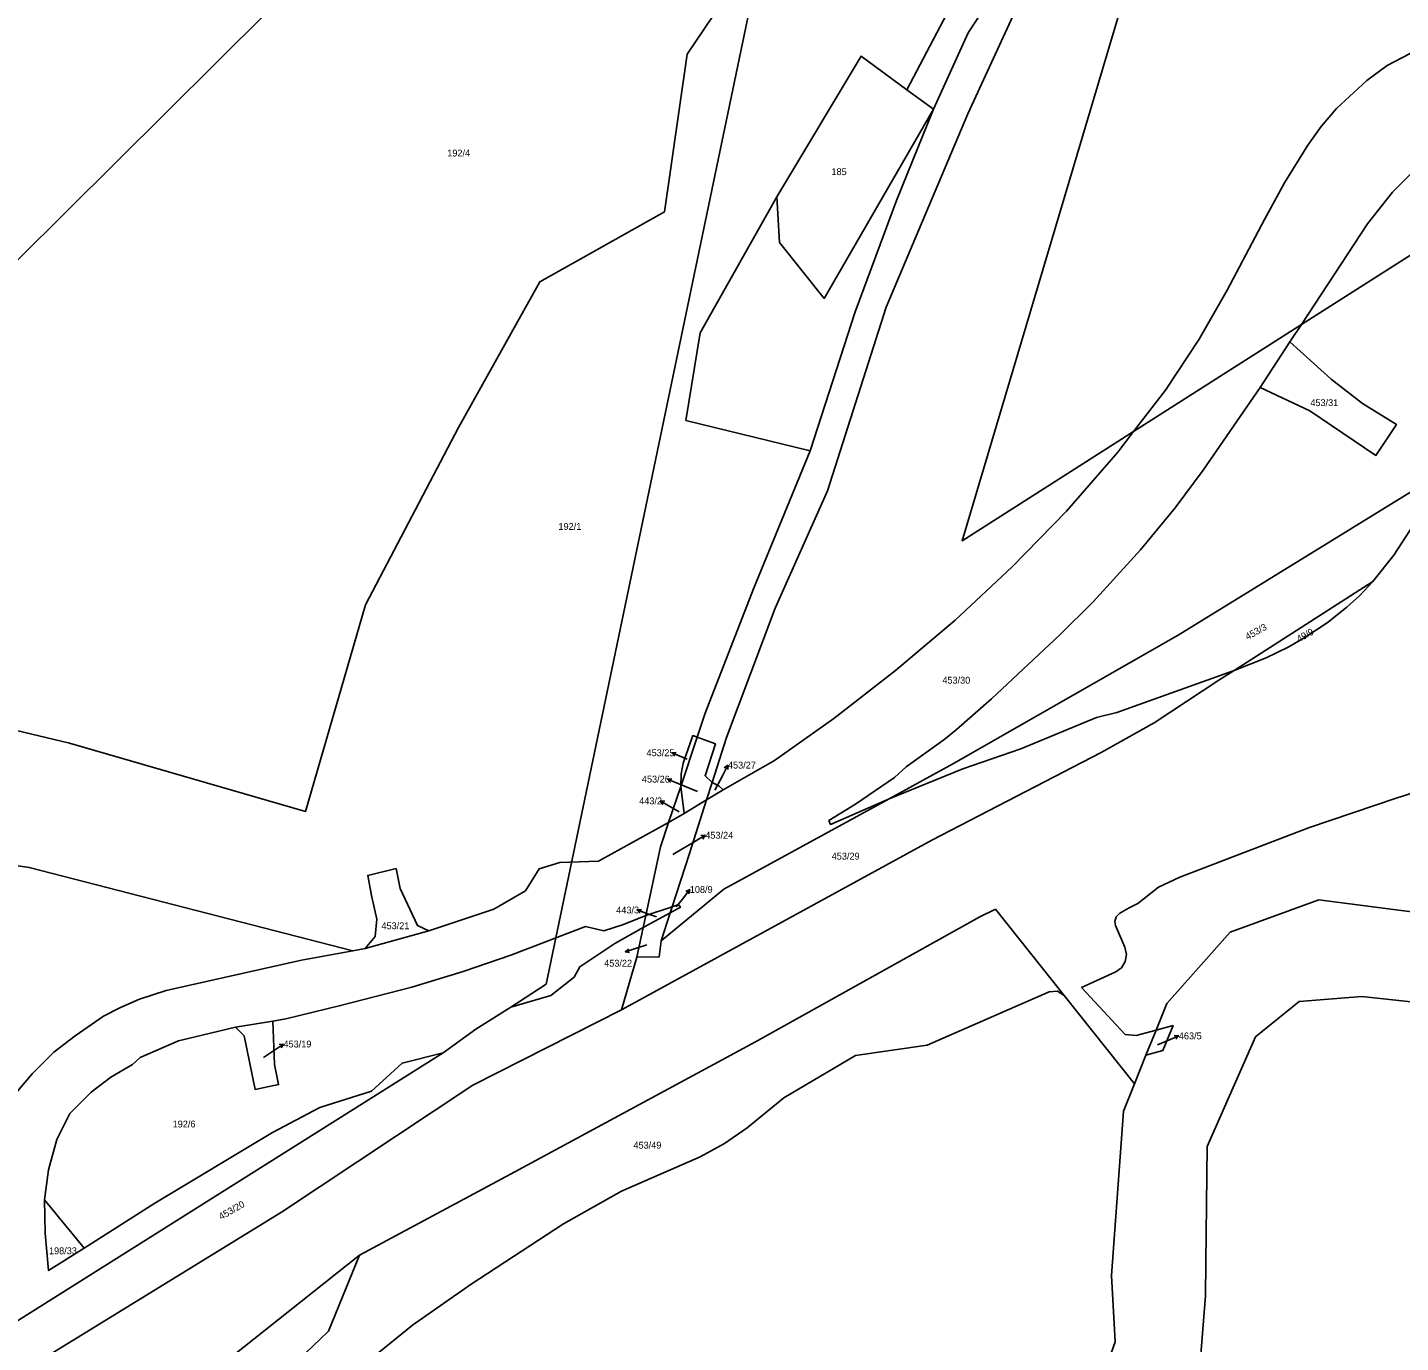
# Model space of a CAD drawing. Extents: x -882150 to -879379, y -1022570 to -1019819.
# Drawn here: x -880457.2 to -880115.3, y -1021005.3 to -1020677.8 of the extents above; entities that cross this region are included whole.
import ezdxf

# ---------------------------------------------------------------- set-up
doc = ezdxf.new("R2010")
doc.units = 0
for name, color, linetype in [('Hranice parcel', 7, 'Continuous'), ('Parcelní čísla', 7, 'Continuous'), ('Pop  PČ popisy', 7, 'Continuous'), ('Vnitřní kresba', 7, 'Continuous')]:
    doc.layers.add(name, color=color, linetype=linetype)

msp = doc.modelspace()

# ---------------------------------------------------------------- linework, layer by layer
at = {"layer": 'Hranice parcel'}
for p, q in [((-880238.27, -1020693.28), (-880231.63, -1020698.12)), ((-880181.75, -1020778.37), (-880139.93, -1020751.73)), ((-880139.93, -1020751.73), (-880142.83, -1020756.07)), ((-880142.83, -1020756.07), (-880150.22, -1020767.47)), ((-880122.17, -1020815.79), (-880156.76, -1020837.93)), ((-880294.53, -1020866.79), (-880290.44, -1020854.54)), ((-880294.53, -1020866.79), (-880297.54, -1020875.81)), ((-880293.68, -1020873.57), (-880294.53, -1020866.79)), ((-880288.1, -1020870.15), (-880286.7, -1020865.81)), ((-880288.1, -1020870.15), (-880283.97, -1020867.62)), ((-880293.68, -1020873.57), (-880288.1, -1020870.15)), ((-880297.54, -1020875.81), (-880293.68, -1020873.57)), ((-880303.88, -1020901.94), (-880297.16, -1020898.25)), ((-880303.88, -1020901.94), (-880303.23, -1020898.93)), ((-880296.68, -1020896.77), (-880303.23, -1020898.93)), ((-880299.42, -1020905.23), (-880297.16, -1020898.25)), ((-880296.68, -1020896.77), (-880297.16, -1020898.25)), ((-880216.12, -1020897.39), (-880199.05, -1020918.85)), ((-880373.11, -1020907.18), (-880357.27, -1020902.75)), ((-880305.47, -1020909.34), (-880303.88, -1020901.94)), ((-880376.21, -1020907.74), (-880373.11, -1020907.18)), ((-880309.24, -1020922.47), (-880305.47, -1020909.34)), ((-880181.53, -1020940.86), (-880199.05, -1020918.85)), ((-880140.53, -1020920.39), (-880124.94, -1020919.09)), ((-880396.06, -1020925.22), (-880405.41, -1020926.73)), ((-880176.17, -1020927.49), (-880178.69, -1020933.76)), ((-880181.53, -1020940.86), (-880178.69, -1020933.76)), ((-880452.92, -1020969.75), (-880443.03, -1020981.82)), ((-880163.83, -1020993.67), (-880163.75, -1020985.47))]:
    msp.add_line(p, q, dxfattribs=at)
for points in [[(-880181.75, -1020778.37), (-880224.49, -1020805.59), (-880179.88, -1020655.79), (-880135.29, -1020506), (-880090.68, -1020356.2)], [(-880169.37, -1020529.41), (-880177.43, -1020555.79), (-880182.92, -1020584.5), (-880189.9, -1020614), (-880200.18, -1020646.83), (-880206.84, -1020664.08), (-880223.08, -1020699.25), (-880243.38, -1020747.4), (-880257.98, -1020793.2), (-880271.05, -1020822.37), (-880283.1, -1020854.61), (-880286.7, -1020865.81)], [(-880360.27, -1020636.82), (-880354.1, -1020637.87), (-880321.84, -1020610.85), (-880294.54, -1020587.99), (-880281.75, -1020603.26), (-880254.56, -1020635.3), (-880265.26, -1020654.96), (-880284.47, -1020671.92), (-880292.9, -1020684.4), (-880298.58, -1020723.73), (-880329.61, -1020741.11), (-880349.9, -1020777.37), (-880372.99, -1020821.6), (-880387.98, -1020873.06), (-880446.75, -1020856.01), (-880505.51, -1020841.96)], [(-880360.27, -1020636.82), (-880459.8, -1020735.88), (-880505.51, -1020841.96)], [(-880210.36, -1020645.27), (-880221.64, -1020661.69), (-880238.27, -1020693.28)], [(-880231.63, -1020698.12), (-880222.93, -1020679.1), (-880211.66, -1020661.81), (-880205.85, -1020646.77)], [(-880111.13, -1020683.34), (-880118.61, -1020687.27), (-880123.66, -1020691.01), (-880131.25, -1020697.94), (-880135.05, -1020702.48), (-880138.42, -1020707.13), (-880144.23, -1020716.46), (-880149.21, -1020725.58), (-880158.47, -1020743.21), (-880165.4, -1020755.39), (-880173.83, -1020768.13), (-880181.75, -1020778.37)], [(-880238.27, -1020693.28), (-880249.64, -1020684.93), (-880270.59, -1020719.96)], [(-880290.44, -1020854.54), (-880288.44, -1020848.53), (-880276.39, -1020817.55), (-880262.3, -1020783.21), (-880251.07, -1020748.62), (-880240.78, -1020720.89), (-880231.63, -1020698.12)], [(-880270.59, -1020719.96), (-880269.91, -1020731.31), (-880258.78, -1020745.24), (-880231.63, -1020698.12)], [(-880070.77, -1020713.27), (-880069.41, -1020711.42), (-880069.23, -1020708.91), (-880070.33, -1020706.52), (-880072.26, -1020705.33), (-880078.68, -1020703.61), (-880086.33, -1020703.09), (-880092.94, -1020703.88), (-880100.29, -1020706.14), (-880106.13, -1020709.1), (-880111.46, -1020713.02), (-880117.31, -1020718.77), (-880123.56, -1020726.71), (-880139.93, -1020751.73)], [(-880139.93, -1020751.73), (-880094.28, -1020722.66), (-880085.25, -1020734.33)], [(-880150.22, -1020767.47), (-880137.88, -1020773.22), (-880121.41, -1020784.35), (-880116.31, -1020776.65), (-880124.8, -1020771.46), (-880132.61, -1020765.33), (-880142.83, -1020756.07)], [(-880150.22, -1020767.47), (-880164.46, -1020787.99), (-880171.43, -1020797.37), (-880180.08, -1020807.88), (-880191.83, -1020820.82), (-880200.11, -1020829.08), (-880217.14, -1020844.96), (-880225.91, -1020852.71), (-880229.02, -1020855.16), (-880238.4, -1020861.93), (-880241.26, -1020864.61), (-880251, -1020871.19), (-880257.64, -1020875.29), (-880257.26, -1020876.25), (-880242.62, -1020869.86)], [(-880283.97, -1020867.62), (-880271.21, -1020860.33), (-880256.37, -1020849.85), (-880241.06, -1020837.88), (-880226.22, -1020825.37), (-880212.01, -1020812.14), (-880198.47, -1020798.2), (-880185.73, -1020783.52), (-880181.75, -1020778.37)], [(-880242.62, -1020869.86), (-880226.61, -1020861.09), (-880170.66, -1020829.12), (-880104.98, -1020788.72)], [(-880104.98, -1020788.72), (-880110.84, -1020799.71), (-880116.96, -1020809.22), (-880122.17, -1020815.79)], [(-879855.67, -1020806.93), (-879897.91, -1020816.71), (-879991.04, -1020835.27), (-880061.88, -1020853.33), (-880091.47, -1020861.88), (-880116.15, -1020869.62), (-880138.18, -1020877.13), (-880170.25, -1020889.4), (-880175.6, -1020891.87), (-880180.75, -1020895.93), (-880182.85, -1020897), (-880185.19, -1020898.34), (-880186.1, -1020899.24), (-880186.44, -1020900.39), (-880186.27, -1020901.44), (-880183.95, -1020906.85), (-880183.54, -1020908.65), (-880183.84, -1020910.43), (-880184.81, -1020911.94), (-880186.2, -1020912.94), (-880194.71, -1020916.87), (-880183.87, -1020928.56), (-880181.15, -1020928.81), (-880176.17, -1020927.49)], [(-880176.17, -1020927.49), (-880173.52, -1020920.87), (-880157.73, -1020903.11), (-880135.62, -1020895), (-880066.31, -1020904.04), (-880020.56, -1020909.99), (-879978.51, -1020931.21), (-879954.91, -1020940.95), (-879934.91, -1020941.76), (-879915.17, -1020933.91), (-879891.35, -1020908.94), (-879871.04, -1020869.47), (-879858.22, -1020838.74), (-879867.14, -1020822.1), (-879855.67, -1020806.93)], [(-880156.76, -1020837.93), (-880148.73, -1020834.8), (-880143.26, -1020832.13), (-880139.12, -1020829.73), (-880133.59, -1020826.04), (-880128.64, -1020822.14), (-880125.43, -1020819.23), (-880122.17, -1020815.79)], [(-880156.76, -1020837.93), (-880160.51, -1020840.33), (-880176.62, -1020850.96), (-880189.88, -1020858.38), (-880232.02, -1020880.14), (-880309.24, -1020922.47)], [(-880242.62, -1020869.86), (-880224.31, -1020862.41), (-880209.84, -1020857.43), (-880190.99, -1020849.61), (-880185.98, -1020848.36), (-880156.76, -1020837.93)], [(-880290.44, -1020854.54), (-880291.53, -1020854.15), (-880293.93, -1020861.01), (-880294.41, -1020863.62), (-880294.53, -1020866.79)], [(-880286.7, -1020865.81), (-880288.47, -1020864.12), (-880285.87, -1020856.15), (-880290.44, -1020854.54)], [(-880283.97, -1020867.62), (-880285, -1020866.63), (-880286.7, -1020865.81)], [(-880517.75, -1020870.05), (-880517.49, -1020870.11), (-880505.07, -1020880.11), (-880491.9, -1020885.09), (-880485.69, -1020882.64), (-880456.73, -1020886.98), (-880376.21, -1020907.74)], [(-880242.62, -1020869.86), (-880283.79, -1020892.4), (-880299.42, -1020905.23)], [(-880296.68, -1020896.77), (-880292.38, -1020883.47), (-880288.1, -1020870.15)], [(-880357.27, -1020902.75), (-880341.1, -1020897.36), (-880333.18, -1020892.77), (-880329.77, -1020887.29), (-880324.59, -1020885.71), (-880314.97, -1020885.37), (-880297.54, -1020875.81)], [(-880303.23, -1020898.93), (-880299.56, -1020881.85), (-880297.54, -1020875.81)], [(-880357.27, -1020902.75), (-880360.03, -1020901.45), (-880364.41, -1020892.19), (-880365.39, -1020887.26), (-880372.44, -1020888.94), (-880371.54, -1020893.97), (-880370.18, -1020899.85), (-880370.57, -1020904.19), (-880373.11, -1020907.18)], [(-880303.23, -1020898.93), (-880308.74, -1020901.14), (-880313.66, -1020902.75), (-880318.22, -1020901.68), (-880336.8, -1020908.79), (-880348.72, -1020912.89), (-880361.47, -1020916.77), (-880379.22, -1020921.37), (-880392.88, -1020924.69), (-880396.06, -1020925.22)], [(-880374.5, -1020983.56), (-880336.91, -1020963.36), (-880275.89, -1020930.37), (-880220.08, -1020899.26), (-880216.12, -1020897.39)], [(-880297.16, -1020898.25), (-880294.62, -1020896.87), (-880295.09, -1020896.22), (-880296.68, -1020896.77)], [(-880443.03, -1020981.82), (-880425.47, -1020970.54), (-880396.18, -1020953.01), (-880384.39, -1020946.77), (-880371.56, -1020942.65), (-880363.91, -1020935.7), (-880353.65, -1020933.14), (-880345.53, -1020927.28), (-880336.82, -1020921.74), (-880326.9, -1020918.86), (-880321.06, -1020914.29), (-880319.61, -1020911.72), (-880310.91, -1020905.88), (-880303.88, -1020901.94)], [(-880305.47, -1020909.34), (-880299.93, -1020909.24), (-880299.42, -1020905.23)], [(-880461.45, -1020945.38), (-880459.21, -1020942.16), (-880455.97, -1020938.25), (-880450.62, -1020932.96), (-880445.34, -1020928.88), (-880438.23, -1020924.03), (-880433.98, -1020921.88), (-880429.27, -1020919.8), (-880422.63, -1020917.62), (-880388.94, -1020910.08), (-880376.21, -1020907.74)], [(-880199.05, -1020918.85), (-880200.75, -1020917.75), (-880202.77, -1020917.97), (-880233.19, -1020931.27), (-880251.05, -1020933.81), (-880268.87, -1020944.34), (-880277.99, -1020951.78), (-880283.59, -1020955.76), (-880289.65, -1020959.07), (-880309.25, -1020967.57), (-880323.7, -1020975.72), (-880346.68, -1020990.73), (-880361.3, -1021000.94), (-880371.02, -1021008.81), (-880386.57, -1021024.64)], [(-880124.94, -1020919.09), (-880036, -1020928.73), (-880013.41, -1020937.59)], [(-880309.24, -1020922.47), (-880346.3, -1020941.23), (-880393.91, -1020972.78), (-880481.22, -1021026.44)], [(-880163.75, -1020985.47), (-880163.48, -1020956.44), (-880151.41, -1020929.13), (-880140.53, -1020920.39)], [(-880405.41, -1020926.73), (-880419.61, -1020930.15), (-880429.15, -1020934.34), (-880431.01, -1020936.05), (-880436.4, -1020939.22), (-880441.32, -1020942.92), (-880446.63, -1020948.21), (-880449.85, -1020954.72), (-880451.96, -1020962.25), (-880452.92, -1020969.75)], [(-880396.06, -1020925.22), (-880395.65, -1020936.08), (-880394.64, -1020941.05), (-880400.52, -1020942.24), (-880403.23, -1020928.94), (-880405.41, -1020926.73)], [(-880178.69, -1020933.76), (-880174.48, -1020932.59), (-880171.94, -1020926.36), (-880176.17, -1020927.49)], [(-880352.16, -1021204.62), (-880345.13, -1021178.51), (-880333.62, -1021140.15), (-880320.84, -1021109.45), (-880307.78, -1021088.71), (-880291.73, -1021075.46), (-880275.49, -1021067.81), (-880232.91, -1021051.56), (-880209.2, -1021040.29), (-880193.39, -1021025.06), (-880186.35, -1021005.08), (-880187.25, -1020988.59), (-880184.26, -1020947.68), (-880181.53, -1020940.86)], [(-880452.92, -1020969.75), (-880452.8, -1020978.03), (-880451.91, -1020987.37), (-880443.03, -1020981.82)], [(-880574.71, -1021116.82), (-880511.95, -1021078.31), (-880468.39, -1021050.82), (-880418.11, -1021018.15), (-880374.5, -1020983.56)], [(-880374.5, -1020983.56), (-880382.21, -1021002.48), (-880395.74, -1021015.43), (-880410.24, -1021024.49)], [(-880383.32, -1021590.53), (-880388.97, -1021562.43), (-880390.19, -1021534.27), (-880387.73, -1021505.59), (-880379.83, -1021478.12), (-880354.56, -1021409.73), (-880325.92, -1021331.12), (-880321.65, -1021310.18), (-880321.88, -1021279.76), (-880330.68, -1021225.65), (-880330.04, -1021210.18), (-880313.87, -1021148.79), (-880301.09, -1021117.72), (-880281.33, -1021095.35), (-880255.32, -1021084.31), (-880230.68, -1021082.99), (-880217.42, -1021078.67), (-880186.94, -1021050.63), (-880171.67, -1021029), (-880165.07, -1021009.24), (-880163.83, -1020993.67)]]:
    msp.add_lwpolyline(points, dxfattribs=at)
at = {"layer": 'Pop  PČ popisy'}
for p, q in [((-880296.742, -1020858.436), (-880295.626, -1020858.347)), ((-880293.96, -1020859.56), (-880296.742, -1020858.436)), ((-880296.742, -1020858.436), (-880296.002, -1020859.275)), ((-880292.91, -1020859.99), (-880293.96, -1020859.56)), ((-880284.15, -1020864.15), (-880282.788, -1020861.476)), ((-880282.788, -1020861.476), (-880283.688, -1020862.141)), ((-880282.788, -1020861.476), (-880282.796, -1020862.596)), ((-880297.822, -1020864.996), (-880296.706, -1020864.907)), ((-880295.04, -1020866.12), (-880297.822, -1020864.996)), ((-880297.822, -1020864.996), (-880297.082, -1020865.835)), ((-880286.01, -1020867.73), (-880284.15, -1020864.15)), ((-880290.33, -1020868.06), (-880295.04, -1020866.12)), ((-880297.04, -1020871.89), (-880299.639, -1020870.39)), ((-880299.639, -1020870.39), (-880298.521, -1020870.457)), ((-880299.639, -1020870.39), (-880299.022, -1020871.324)), ((-880294.9, -1020873.13), (-880297.04, -1020871.89)), ((-880296.48, -1020883.77), (-880291, -1020880.49)), ((-880291, -1020880.49), (-880288.428, -1020878.944)), ((-880288.428, -1020878.944), (-880289.544, -1020879.031)), ((-880288.428, -1020878.944), (-880289.028, -1020879.889)), ((-880294.1, -1020894.83), (-880292.252, -1020892.465)), ((-880292.252, -1020892.465), (-880293.264, -1020892.946)), ((-880292.252, -1020892.465), (-880292.474, -1020893.563)), ((-880295.63, -1020896.82), (-880294.1, -1020894.83)), ((-880305.37, -1020897.564), (-880304.258, -1020897.436)), ((-880302.55, -1020898.59), (-880305.37, -1020897.564)), ((-880305.37, -1020897.564), (-880304.6, -1020898.377)), ((-880300.55, -1020899.31), (-880302.55, -1020898.59)), ((-880305.5, -1020907.06), (-880308.354, -1020907.987)), ((-880308.354, -1020907.987), (-880307.556, -1020907.202)), ((-880308.354, -1020907.987), (-880307.247, -1020908.154)), ((-880303, -1020906.27), (-880305.5, -1020907.06)), ((-880175.82, -1020931.16), (-880173.27, -1020930.08)), ((-880173.27, -1020930.08), (-880170.508, -1020928.907)), ((-880170.508, -1020928.907), (-880171.625, -1020928.838)), ((-880170.508, -1020928.907), (-880171.234, -1020929.76)), ((-880398.38, -1020934.27), (-880395.93, -1020932.62)), ((-880395.93, -1020932.62), (-880393.442, -1020930.942)), ((-880393.442, -1020930.942), (-880394.552, -1020931.087)), ((-880393.442, -1020930.942), (-880393.992, -1020931.917))]:
    msp.add_line(p, q, dxfattribs=at)
at = {"layer": 'Vnitřní kresba'}
for p, q in [((-880328, -1020916), (-880253, -1020556)), ((-880289.67, -1020753.8), (-880270.59, -1020719.96)), ((-880293.24, -1020775.66), (-880289.67, -1020753.8)), ((-880293.24, -1020775.66), (-880262.3, -1020783.21)), ((-880336.82, -1020921.74), (-880328, -1020916)), ((-880345.53, -1020927.28), (-880336.82, -1020921.74)), ((-880353.65, -1020933.14), (-880345.53, -1020927.28)), ((-880497.01, -1021023.34), (-880353.65, -1020933.14))]:
    msp.add_line(p, q, dxfattribs=at)

# ---------------------------------------------------------------- texts
at = {"layer": 'Parcelní čísla'}
for s, p in [('192/4', (-880352.66, -1020709.91)), ('185', (-880257, -1020714.55)), ('453/31', (-880137.76, -1020772.07)), ('192/1', (-880324.97, -1020802.9)), ('453/30', (-880229.39, -1020841.19)), ('453/25', (-880303.038, -1020859.26)), ('453/27', (-880282.77, -1020862.34)), ('453/26', (-880304.199, -1020865.83)), ('443/2', (-880304.865, -1020871.24)), ('453/24', (-880288.42, -1020879.8)), ('453/29', (-880256.94, -1020885.01)), ('108/9', (-880292.27, -1020893.3)), ('443/3', (-880310.586, -1020898.42)), ('453/21', (-880369.05, -1020902.35)), ('453/22', (-880313.593, -1020911.668)), ('453/19', (-880393.44, -1020931.8)), ('463/5', (-880170.5, -1020929.77)), ('192/6', (-880421.04, -1020951.72)), ('453/49', (-880306.3, -1020956.99)), ('198/33', (-880451.83, -1020983.29))]:
    msp.add_text(s, height=1.7, dxfattribs=at).set_placement(p)
for s, rotation, p in [('453/3', 29, (-880153.397, -1020830.373)), ('49/9', 29, (-880140.587, -1020830.943)), ('453/20', 30, (-880408.935, -1020974.806))]:
    msp.add_text(s, height=1.7, rotation=rotation, dxfattribs=at).set_placement(p)

doc.saveas('drawing.dxf')
